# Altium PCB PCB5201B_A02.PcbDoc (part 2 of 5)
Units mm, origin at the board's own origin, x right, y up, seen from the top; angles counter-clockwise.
Board outline 115 x 60 mm, 6 copper layers (Top Layer, GND Layer 2, Signal Layer 3, Signal Layer 4, VCC Layer 5, Bottom Layer), stack 1.555 mm thick; 355 components, 250 nets, 1223 pads, 1070 vias.
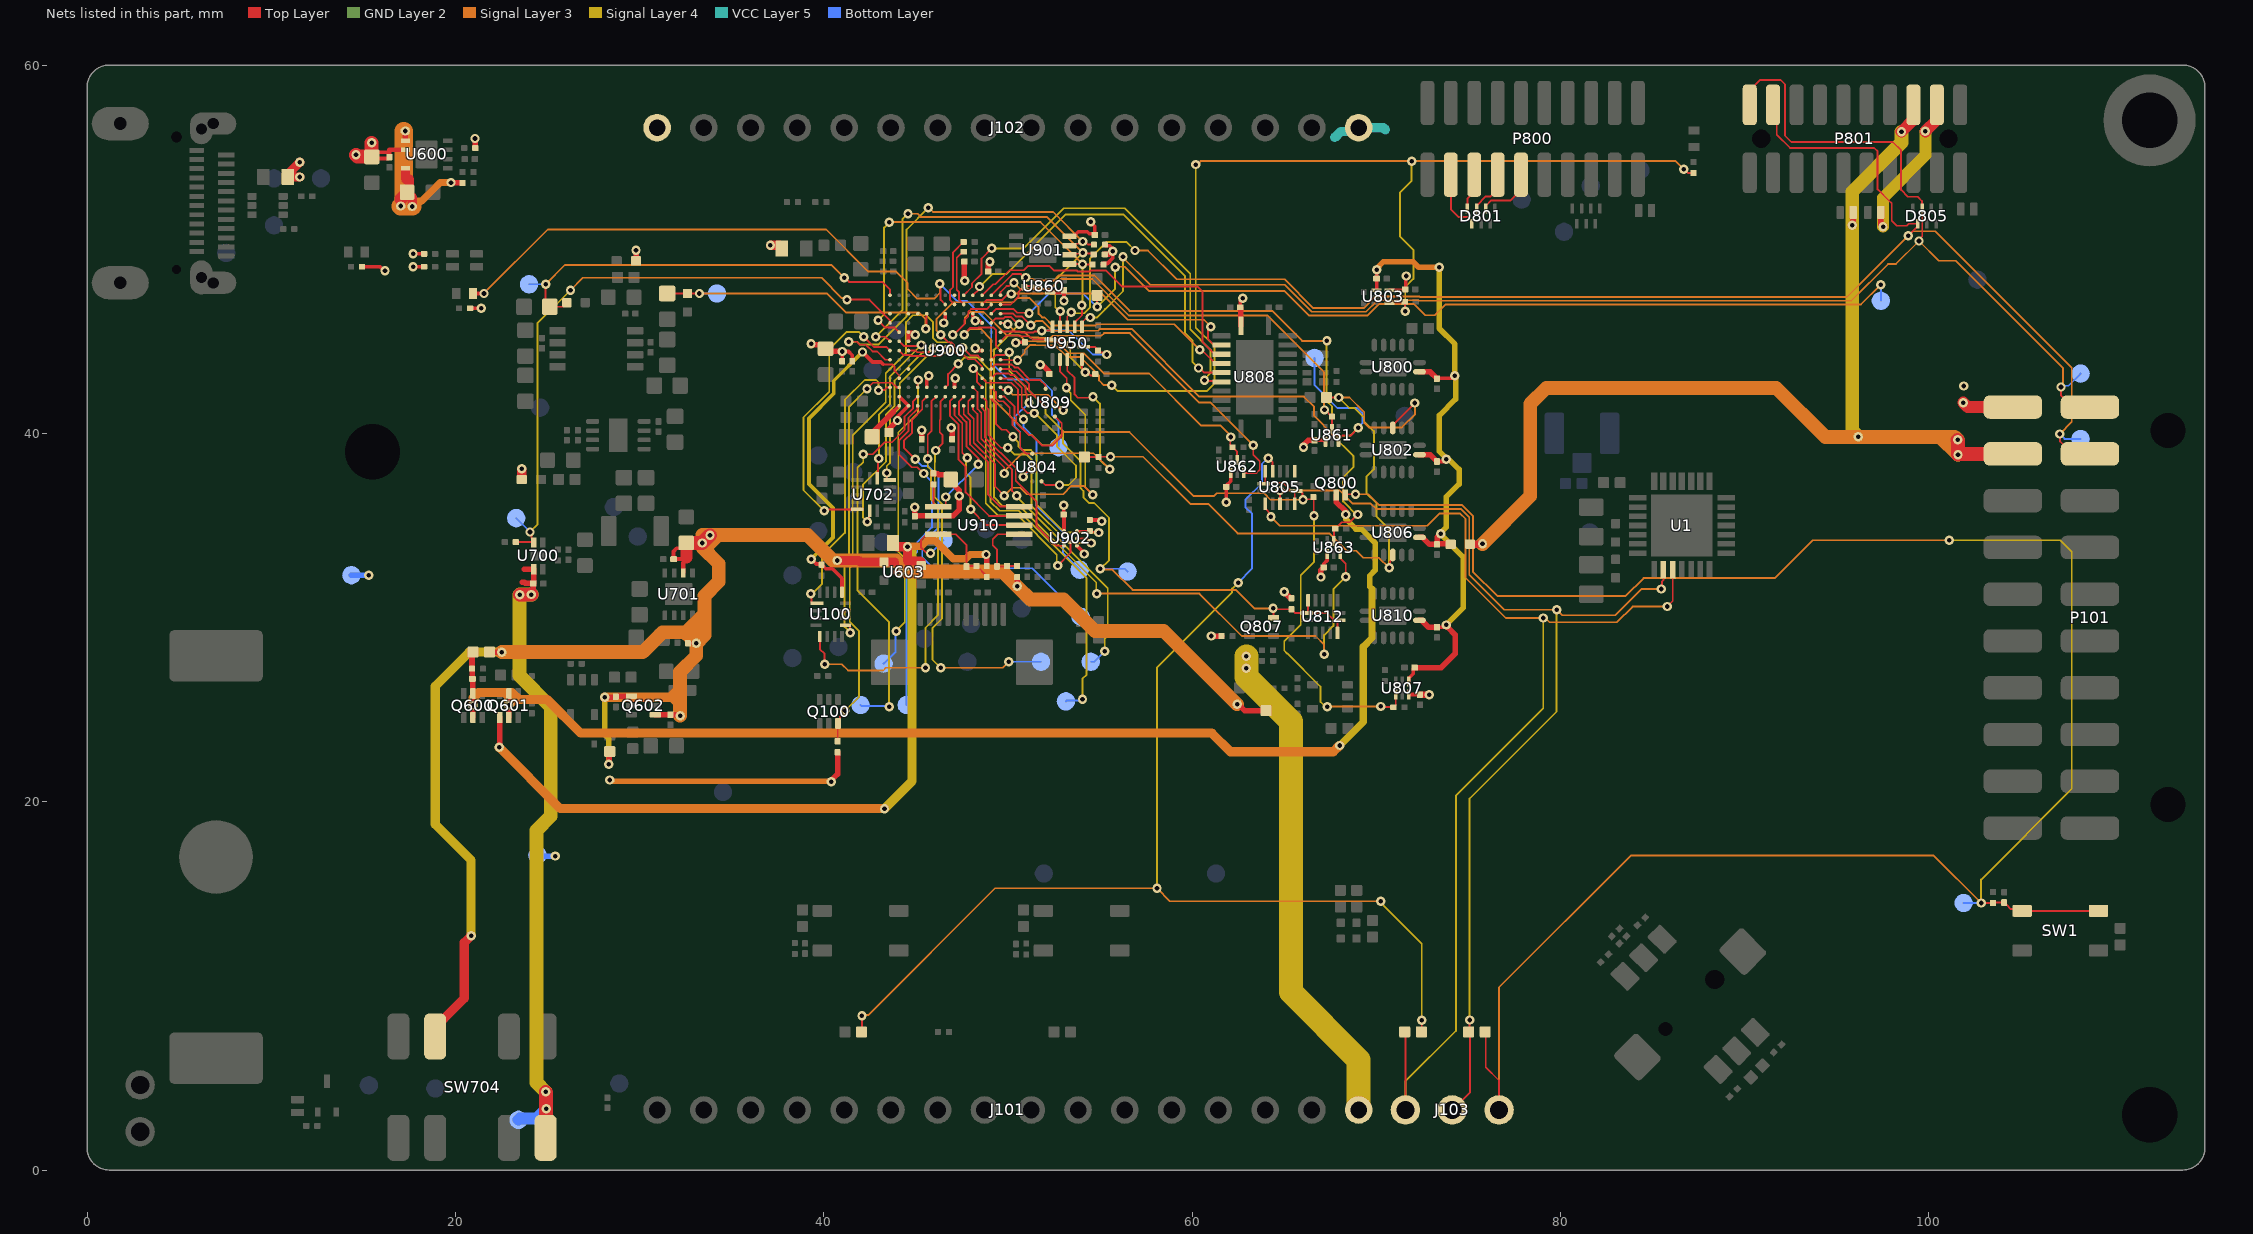
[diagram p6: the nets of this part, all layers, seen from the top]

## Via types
v1: diameter 0.508, hole 0.25, Top Layer to Bottom Layer, tented both sides, 1070 vias

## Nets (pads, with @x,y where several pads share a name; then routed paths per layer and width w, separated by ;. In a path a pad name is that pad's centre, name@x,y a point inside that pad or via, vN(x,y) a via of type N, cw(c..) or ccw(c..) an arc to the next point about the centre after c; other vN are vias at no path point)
3V3: C607.1 C807.1 C808.1 C860.1 C862.1 C864.1 C866.1 C868.1 C907.1 C908.1 C909.1 C910.1 C911.1 C914.1 C921.1 C922.1 C924.1 C925.1 C926.1 C927.1 C951.1 D807.1 J101.16 J102.16 L704.1 L900.1 P101.20 P801.3 R142.2 R601.2 R838.2 R840.2 R903.1 R906.2 R907.1 R908.1 R909.1 R912.1 R919.1 R920.1 R982.1 TPJ600.1 TPJ950.1 U600.1 U600.4 U803.6 U807.6 U808.1 U860.1 U861.1 U862.1 U863.1 U900.C6 U900.C9 U900.G3 U900.H11 U900.J11 U900.K3 U900.L4 U900.L7 U901.8 U902.A1 U902.E3 U910.2 | length 110.9
  Top Layer w0.2: R903.1@14.925,49.05 15.904,49.05 16.129,48.825 v1(16.175,48.825) ; U600.1@17.282,55.897 17.282,56.047 ; v1(17.7,49.05) R919.1@18.3,49.05 ; v1(17.7,49.75) R920.1@18.3,49.75 ; R912.1@20.8,46.8 v1(21.4,46.8) ; C924.1@41,43.925 41,44.325 41.125,44.45 41.35,44.45 41.55,44.25 C925.1@41.55,43.925 ; U900.H11@44.6,45 U900.J11@44.6,45.5 44.8,45.5 44.942,45.358 v1(44.974,45.358) ; U900.C9@45.6,42.5 45.6,43.025 v1(45.7,43.125) ; v1(46.525,46) 46.55,46 46.6,46.05 U900.L7@46.6,46.5 ; U900.C6@47.1,42.5 47.1,42.925 v1@47.175,43 ; U900.L4@48.1,46.5 48.1,46.35 48.25,46.2 48.25,46.15 v1(48.225,46.125) 48.475,46.125 U900.K3@48.6,46 ; v1(48.225,44.625) 48.35,44.5 U900.G3@48.6,44.5 ; v1(50.425,44.925) 50.45,44.95 C911.1@50.925,44.95 ; U860.1@52.3,47.65 52.925,47.65 C862.1@53.05,47.775 53.05,47.204 v1(53.047,47.201) ; v1@52.9,36.1 53.025,35.975 C914.1@53.025,35.6 53.05,35.575 U902.A1@53.05,34.7 ; U901.8@53.475,50.7 53.57,50.7 53.82,50.95 54.3,50.95 54.412,50.838 54.662,50.838 C951.1@54.722,50.778 54.722,51.238 54.55,51.411 v1@54.55,51.435 ; U902.E3@53.75,33.9 53.75,33.897 54.145,33.502 v1(54.145,33.455) ; R906.2@54.45,35.3 55.025,35.3 v1(55.1,35.225) ; v1(54.498,51.502) 54.498,51.487 v1@54.55,51.435 ; v1@54.55,51.475 v1@54.55,51.435 ; v1@54.625,51.36 v1@54.55,51.435 ; R908.1@55.139,49.175 55.192,49.228 55.403,49.228 55.696,49.521 55.696,49.896 v1(55.7,49.9) ; R909.1@55.25,50.225 55.284,50.191 55.53,50.191 55.725,49.996 v1@55.725,49.9 ; v1(61.866,36.253) 61.858,36.261 61.858,37.092 C860.1@61.85,37.1 61.85,37.15 62.1,37.4 U862.1@62.1,37.85 ; C808.1@62.625,46.85 62.625,47.225 v1(62.75,47.35) ; C864.1@66.65,39.625 67.175,39.625 U861.1@67.25,39.55 ; C866.1@67.15,32.725 67.15,32.925 67.35,33.125 U863.1@67.35,33.45 ; U803.6@70.725,47.775 71.495,47.775 71.5,47.78 C807.1@71.5,47.825 ; C807.1@71.575,47.825 71.6,47.85 71.6,48.525 v1(71.625,48.55) ; U807.6@71.763,25.825 71.763,25.82 72.319,25.82 C868.1@72.325,25.825
  Top Layer w0.25: 17.282,54.247 U600.4@17.282,54.397
  Top Layer w0.3: 17.282,56.047 v1(17.282,56.422) ; v1(19.757,53.622) 19.77,53.61 20.372,53.61 R601.2@20.382,53.597 R601.2@20.382,53.597 ; v1(39.312,44.865) 39.352,44.825 39.875,44.825 40.25,44.45 v1(41,44.45) v1@41.125,44.45 ; v1(40.4,21.085) 40.4,21.141 40.756,21.497 R142.2@40.756,22.683 ; v1(44.95,36) C922.1@44.95,35.5 44.975,35.525 U910.2@46.225,35.525 47.025,35.525 47.35,35.85 47.35,36.925 C921.1@46.825,37.45 ; C927.1@45.325,39.675 v1(45.325,40.175) ; R982.1@45.954,37.831 45.954,37.821 45.964,37.811 46.189,37.811 46.25,37.75 46.65,37.75 C921.1@46.9,37.5 ; v1(46.925,40.3) 46.975,40.25 C926.1@46.975,39.675 ; v1@47.634,48.316 C910.1@47.634,49.333 ; C908.1@48.925,48.8 48.925,49.225 v1(49.025,49.325) ; v1(51.748,43.738) 51.788,43.699 51.9,43.699 52.225,43.374 52.225,43.234 52.235,43.224 C909.1@52.255,43.224 ; R907.1@55.265,49.726 55.275,49.736 55.479,49.736 55.604,49.86 v1@55.665,49.86 ; v1(61.05,29) 61.052,28.998 61.599,28.998 R838.2@61.601,28.996 ; C808.1@62.625,46.85 62.65,46.825 U808.1@62.65,45.845 ; v1(65,31.4) 65.35,31.05 R840.2@65.4,31.05 ; v1(66.05,39.25) 66.05,39.375 66.3,39.625 C864.1@66.65,39.625 ; v1(67,32.2) 67,32.575 C866.1@67.15,32.725 ; D807.1@97.4,52 97.4,51.35 v1(97.525,51.225) ; L704.1@29.807,49.375 v1(29.807,49.95) L704.1@29.807,49.375
  Top Layer w0.35: C868.1@72.376,25.814 72.381,25.809 72.866,25.809 v1(72.875,25.8)
  Top Layer w0.5: v1(17.032,52.347) 17.034,52.349 C607.1@17.034,52.724 ; 17.282,53.8 17.282,54.247 ; C607.1@17.382,53.072 C607.1@17.382,53.097 ; 17.5,53.8 17.5,53.215 C607.1@17.382,53.097 ; v1(17.657,52.322) 17.657,52.822 C607.1@17.382,53.097 ; v1(37.106,50.217) 37.107,50.215 37.615,50.215 L900.1@37.814,50.016
  Top Layer w0.635: v1(99.825,56.4) 100.445,57.02 P801.3@100.445,57.841 ; v1(101.875,41.675) 102.12,41.43 P101.20@104.57,41.43
  Top Layer w0.7: C607.1@17.034,52.724 C607.1@17.382,53.072
  Signal Layer 3 w0.3: 17.25,53.225 17.85,52.625 ; v1(17.657,52.322) 17.697,52.362 17.912,52.362 18.175,52.625 ; v1(28.372,21.181) 28.411,21.142 28.558,21.142 28.576,21.124 v1@40.349,21.124
  Signal Layer 3 w0.4: 17.85,52.625 18.175,52.625 19.172,53.622 v1(19.757,53.622)
  Signal Layer 3 w1: v1@17.03,52.345 17.053,52.322 v1(17.657,52.322) ; 17.191,52.788 v1@17.191,56.422
  Signal Layer 4 w0.635: v1(97.525,51.225) 97.525,52.8 99.825,55.1 v1(99.825,56.4)
  Signal Layer 4 w1.3: v1(62.95,27.9) v1(62.95,27.25) 62.95,26.775 65.375,24.35 65.375,9.658 69.05,5.983 J101.16@69.05,3.262
  VCC Layer 5 w0.508: 67.759,56.076 68.076,56.393 68.841,56.393 J102.16@69.05,56.602 ; J102.16@68.877,56.602 J102.16@69.05,56.602 ; 70.5,56.5 70.398,56.602 J102.16@69.05,56.602
  Bottom Layer w0.3: TPJ600.1@14.353,32.302 v1(15.3,32.3) ; TPJ950.1@24.452,17.1 24.502,17.05 v1(25.425,17.05)
  other v1: 53.025,36.1 47.35,36.6 101.9,42.575 47.15,43 47.65,48.3
3V6_SW: C608.1 L702.1 Q601.1 R639.2 U603.B1 | length 47.3
  Top Layer w0.2: U603.B1@44.55,32.65 44.55,33.075
  Top Layer w0.3: v1@22.4,22.95 Q601.1@22.4,24.575 ; v1(48.815,33.427) 48.84,33.402 48.84,32.81 R639.2@48.85,32.8
  Top Layer w0.5: L702.1@43.765,34.05 43.965,33.85 v1(44.55,33.85) 44.55,33.075 45.225,33.075 C608.1@45.3,33
  Signal Layer 3 w0.4: v1(44.55,33.85) 44.571,33.871 45.3,33.871 45.604,34.175 46.05,34.175 47.025,33.2 47.725,33.2 47.952,33.427 v1(48.815,33.427)
  Signal Layer 3 w0.5: v1(22.375,22.95) 25.7,19.625 v1(43.3,19.625)
  Signal Layer 4 w0.5: v1(43.3,19.625) 44.8,21.125 44.8,33.598 44.55,33.848 v1(44.55,33.85)
3V6_SW_SENSE: C641.1 R639.1 R640.2 TP923.1 U910.4 | length 7.4
  Top Layer w0.1: v1(45.8,33.5) 45.6,33.5 45.275,33.825 45.275,34.2 45.6,34.525 U910.4@46.225,34.525 47.175,34.525 47.75,33.95 C641.1@47.75,32.775 47.775,32.8 R640.2@48.3,32.8 48.85,32.25 R639.1@48.85,32.2
  Bottom Layer w0.1: v1(45.8,33.5) TP923.1@46.5,34.2
5V: C600.1 C609.1 C611.1 C673.1 C674.1 C702.1 C703.1 C901.1 D806.1 J102.1 L600.2 L700.1 L800.1 P101.18 P801.5 Q602.1 Q602.4 R600.2 R622.2 R633.2 R681.2 R690.2 R700.2 SW704.6 U600.2 U603.A2 U603.B2 U701.2 U900.A11 U900.B12 | length 180.2
  Top Layer w0.2: C611.1@15.453,55.025 cw(c15.546,54.848) C611.1@15.592,55.042 ; 16.417,55.397 16.417,55.275 ; C702.1@31.845,33.231 31.845,33.595 32.011,33.761 32.311,33.761 C703.1@32.4,33.85 ; C702.1@31.858,33.185 32.512,33.185 32.475,33.075 32.375,32.975 ; R700.2@32.627,28.611 32.632,28.606 33.069,28.606 v1(33.075,28.6) ; 43.85,33.025 44.15,32.725 U603.B2@44.15,32.65 44.025,32.65 43.9,32.525 43.9,32.375 44.025,32.25 U603.A2@44.15,32.25 ; v1(44.002,40.702) 44.002,40.902 U900.A11@44.6,41.5 U900.B12@44.1,42 ; 16.417,55.275 16.417,54.985 16.357,54.925 15.554,54.925 C611.1@15.465,55.014 15.725,55.275 16.417,55.275
  Top Layer w0.25: 16.417,55.397 U600.2@17.282,55.397 ; U701.2@32.375,32.425 32.375,32.975
  Top Layer w0.3: v1(20.85,12.725) v1@20.852,12.723 ; v1(21.061,56.017) 21.072,56.007 21.072,55.507 R600.2@21.082,55.497 ; R622.2@21.85,28.125 v1(22.525,28.125) ; v1(28.1,25.675) 28.111,25.686 28.703,25.686 C674.1@28.713,25.697 ; v1(28.335,22.042) 28.357,22.065 28.357,22.699 R681.2@28.38,22.722 ; C674.1@28.713,25.697 28.713,25.715 28.723,25.725 Q602.1@29.55,25.725 ; Q602.4@30.85,24.725 C673.1@31.675,24.725 ; C673.1@31.675,24.721 31.685,24.711 32.105,24.711 32.145,24.671 v1(32.201,24.671) ; C901.1@43.55,40.05 43.55,40.25 v1(44.002,40.702) ; v1(50.5,31.7) R633.2@50.5,32.2 ; v1(62.447,25.294) 62.503,25.294 62.853,24.944 R690.2@64.021,24.944 ; v1(95.85,51.3) 95.9,51.35 D806.1@95.9,52
  Top Layer w0.4: L800.1@75.099,33.978 75.753,33.978 v1(75.775,34)
  Top Layer w0.5: L600.2@10.9,53.926 v1@11.549,53.926 ; L600.2@10.9,53.926 10.985,54.011 10.985,54.156 v1(11.551,54.722) ; SW704.6@18.9,7.25 18.9,7.873 19.246,8.219 19.369,8.219 20.475,9.325 20.475,12.35 v1@20.825,12.7 ; L700.1@23.6,37.5 v1(23.6,38.075) ; v1(40.74,33.1) 41.919,33.1 41.994,33.025 C609.1@43.275,33.025 43.85,33.025
  Top Layer w0.635: v1(98.525,56.375) 99.175,57.025 P801.5@99.175,57.841
  Top Layer w0.65: 32.55,33.25 C703.1@32.55,34.047
  Top Layer w0.75: v1(14.6,55.125) 14.686,55.039 15.44,55.039 C611.1@15.45,55.029 ; v1(15.45,55.775) C611.1@15.45,55.029 ; C611.1@15.465,55.014 C611.1@15.45,55.029 ; C703.1@32.535,34.061 C703.1@32.547,34.05 ; C703.1@32.55,34.047 C703.1@32.547,34.05 ; v1(33.825,34.475) v1(33.4,34.05) C703.1@32.547,34.05 ; v1@101.55,39.65 101.595,39.605 v1(101.595,38.84) 101.644,38.89 P101.18@104.57,38.89
  Signal Layer 3 w0.5: v1(28.1,25.675) 31.65,25.675 ; 32.075,26.15 32.075,26.1 31.65,25.675 ; 32.175,25.25 31.75,25.675 ; 32.201,25.675 31.75,25.675 ; 31.65,25.675 31.75,25.675
  Signal Layer 3 w0.75: v1(22.525,28.125) 30.175,28.125 31.25,29.2 32.475,29.2 ; v1(32.201,24.671) 32.201,25.675 32.201,27.051 33.075,27.925 v1@33.075,28.525 ; 33.5,29.95 33.5,29.55 32.812,28.863 ; 33.5,30.175 32.525,29.2 32.475,29.2 ; v1(33.825,34.475) v1@33.833,34.483 ; 34.575,34.475 34.25,34.475 33.6,33.825 v1@33.4,33.825 ; v1(62.447,25.294) 61.66,26.081 58.466,29.275 54.725,29.275 53.018,30.982 51.218,30.982 v1(50.5,31.7) 49.7,32.5 44.525,32.5 43.925,33.1 v1(40.74,33.1) 40.5,33.1 39.117,34.483 v1@33.833,34.483 ; v1(75.775,34) 78.362,36.587 78.362,41.602 79.235,42.475 91.725,42.475 94.39,39.81 100.625,39.81 ; v1@101.45,39.775 101.415,39.81 100.625,39.81 ; v1@101.576,38.976 v1(101.576,39.665) ; v1(101.595,38.84) 100.625,39.81 ; 32.475,29.2 32.812,28.863 ; 32.812,28.863 v1(33.075,28.6) 33.086,28.6 33.525,29.039 33.525,31.175 34.3,31.95 34.3,32.925 v1@33.4,33.825 ; v1@33.4,33.825 v1(33.4,34.05) 33.4,34.483 v1@33.833,34.483
  Signal Layer 4 w0.3: v1(28.1,25.675) 28.1,23.65 28.335,23.415 v1(28.335,22.042)
  Signal Layer 4 w0.5: v1(20.85,12.725) 20.85,16.825 18.9,18.775 18.9,26.275 20.75,28.125 v1(22.525,28.125)
  Signal Layer 4 w0.75: v1(96.175,39.825) 95.85,40.15 v1(95.85,51.3) 95.85,53.125 98.525,55.8 v1(98.525,56.375)
  other v1: 11.55,53.925
5V_DH_SW: C803.1 C805.1 C809.1 C827.1 C869.1 C870.1 L800.2 U800.14 U802.14 U803.1 U806.14 U807.1 U810.14 | length 39.9
  Top Layer w0.2: C869.1@70.019,48.403 70.022,48.406 70.022,48.89 v1(70.025,48.893) ; U803.1@70.025,47.775 70.022,47.775 70.022,48.347 C869.1@70.025,48.35 ; U807.1@71.763,26.525 71.763,26.7 72.009,26.946 72.009,27.224 72.035,27.25 C870.1@72.075,27.25 ; C827.1@73.3,29.475 73.675,29.475 v1(73.8,29.6) ; C805.1@73.3,38.475 73.675,38.475 v1(73.8,38.6) ; C803.1@73.325,43 74.15,43 v1(74.275,43.125)
  Top Layer w0.3: C870.1@72.089,27.284 73.534,27.284 74.293,28.043 74.293,29.057 73.9,29.45 v1@73.9,29.625 ; U810.14@72.35,29.85 72.475,29.85 72.85,29.475 C827.1@73.3,29.475 ; U806.14@72.35,34.35 72.525,34.35 72.9,33.975 C809.1@73.3,33.975 73.31,33.985 73.31,34.371 73.49,34.551 v1(73.511,34.551) ; U802.14@72.35,38.85 72.925,38.85 C805.1@73.3,38.475 ; U800.14@72.35,43.35 72.925,43.35 C803.1@73.3,42.975 C803.1@73.325,43 ; C809.1@73.31,34 74.028,34 L800.2@74.049,33.978
  Signal Layer 3 w0.3: v1(70.025,48.893) 70.025,48.949 70.157,49.081 70.157,49.097 70.385,49.325 72,49.325 72.3,49.025 v1(73.425,49.025)
  Signal Layer 4 w0.3: v1(73.425,49.025) 73.425,45.7 74.275,44.85 v1(74.275,43.125) 74.315,43.085 74.315,42.938 74.318,42.935 74.318,41.868 73.432,40.982 73.432,39.024 73.8,38.656 v1(73.8,38.6) ; v1(73.8,29.6) 74.725,30.525 74.725,33.3 73.511,34.514 73.511,34.607 73.8,34.897 73.8,36.55 74.5,37.25 74.5,38.05 v1@73.875,38.675
5V_SENSE: C635.1 R633.1 R634.2 U910.7 | length 4.2
  Top Layer w0.1: R633.1@50.5,32.8 R634.2@49.95,32.8 49.925,32.775 C635.1@49.4,32.775 49.4,33.7 49.182,33.918 49.182,34.263 49.444,34.525 U910.7@50.625,34.525
5V_SW: C610.1 Q600.2 Q600.5 Q601.2 Q601.5 Q800.5 R622.1 R623.2 | length 70.9
  Top Layer w0.3: C610.1@20.925,26.675 20.925,27.2 R623.2@20.9,27.225 20.9,28.075 R622.1@20.95,28.125 ; Q600.2@20.95,24.575 v1(20.95,25.225) 20.95,25.25 Q600.5@20.95,25.875 C610.1@20.95,26.65 ; Q601.2@22.9,24.575 v1(22.9,25.25) Q601.5@22.9,25.875 ; Q800.5@67.825,36.65 67.825,36.275 68.35,35.75 v1(68.35,35.6)
  Signal Layer 3 w0.5: v1(20.95,25.225) 20.95,25.626 21.249,25.925 22.675,25.925 22.9,25.7 v1(22.9,25.25) 23.2,25.55 23.45,25.55 ; 22.725,25.925 22.9,25.925 23.075,25.925 23.325,25.675 23.45,25.55 ; v1(68.012,23.052) 67.669,22.709 62.091,22.709 61.075,23.725 26.8,23.725 24.975,25.55 23.45,25.55
  Signal Layer 4 w0.3: v1(68.35,35.6) 68.35,35.35 68.9,34.8 69.2,34.8 69.95,34.05 69.95,32.575 69.643,32.268 69.643,31.682 69.775,31.55
  Signal Layer 4 w0.4: v1(68.012,23.052) 69.307,24.347 69.307,28.425 69.775,28.893 69.775,31.55
#RESET: R805.2 R809.1 R810.2 U802.4 U806.11 | length 39.3
  Top Layer w0.1: R810.2@54.15,38.725 R809.1@54.925,38.725 54.938,38.737 v1(55.575,38.737) ; R805.2@67.3,41.95 v1(67.975,41.95) ; v1(70.7,32.7) 70.748,32.748 70.748,33.023 70.9,33.175 U806.11@70.9,33.4 ; U802.4@70.9,40.3 70.9,40.45 v1(72.1,41.65)
  Signal Layer 3 w0.1: v1(55.575,38.737) 57.338,38.737 59.9,36.175 60.875,36.175 62.475,34.575 67.45,34.575 68.393,33.632 68.918,33.632 69.3,33.25 70.15,33.25 v1(70.7,32.7) ; v1(67.975,41.95) 68.55,41.95 69.35,41.15 69.35,40.575 69.6,40.325 71.4,40.325 72.1,41.025 v1(72.1,41.65)
  Signal Layer 4 w0.1: v1(67.975,41.95) 68.55,41.375 68.825,41.375 69.325,40.875 69.325,40.675 69.875,40.125 69.875,38.05 69.468,37.643 69.468,36.757 70.025,36.2 70.025,35.475 70.7,34.8 v1(70.7,32.7)
AEM_5V_#ENABLE: U900.L10
AEM_CALIBRATE0: U702.13 U900.G11 | length 13.4
  Top Layer w0.1: v1(42.368,35.213) 42.368,35.323 42.45,35.406 42.45,35.74 U702.13@42.5,35.79 ; U900.G11@44.6,44.5 44.992,44.5 45.083,44.409 45.672,44.409 45.863,44.6 v1@45.95,44.6
  Signal Layer 4 w0.1: v1(42.368,35.213) 42.368,35.216 42.125,35.459 42.125,37.214 43.388,38.476 43.388,41.038 43.85,41.5 43.85,42.875 45.375,44.4 45.681,44.4 45.915,44.635 v1(45.935,44.635)
AEM_CALIBRATE1: U702.5 U900.G12 | length 11.9
  Top Layer w0.1: v1(43.425,37.85) 43.425,37.525 43.475,37.475 U702.5@43.585,37.475 ; U900.G12@44.1,44.5 44.35,44.25 44.704,44.25 44.752,44.202 46.327,44.202 v1(46.675,44.55)
  GND Layer 2 w0.1: v1(43.425,37.85) v1@43.483,37.908
  Signal Layer 4 w0.1: v1(43.425,37.85) 43.425,38.231 43.6,38.406 43.6,40.875 44.125,41.4 44.125,42.725 45.593,44.193 46.318,44.193 v1(46.675,44.55)
AEM_CALIBRATE2: U702.6 U900.H12 | length 9.6
  Top Layer w0.1: U702.6@42.9,37.56 42.947,37.607 42.947,38.592 v1(42.995,38.639) ; U900.H12@44.1,45 44.35,44.75 45.25,44.75 v1(45.302,44.802)
  Signal Layer 4 w0.1: v1(42.995,38.639) 42.995,41.003 43.6,41.608 43.6,43.1 v1(45.302,44.802)
AEM_CALIBRATE3: U702.12 U900.G13 | length 15.7
  Top Layer w0.1: v1(40.024,35.799) 40.1,35.875 U702.12@41.815,35.875 ; v1(42.175,45.25) 42.725,44.7 43.4,44.7 U900.G13@43.6,44.5
  Signal Layer 4 w0.1: v1(40.024,35.799) 40.024,35.801 38.9,36.925 38.9,40.867 40.3,42.267 40.3,44.575 41.225,45.5 41.925,45.5 v1(42.175,45.25)
AEM_CURRENT_HIGH_GAIN: C720.1 R764.2 TP706.1 U900.N13 | length 23.2
  Top Layer w0.1: v1(24.9,48.1) 24.9,47.1 R764.2@25.125,46.875 25.825,46.875 C720.1@26.05,47.1 ; v1(41.117,48.445) 41.159,48.445 41.38,48.225 43.175,48.225 43.6,47.8 U900.N13@43.6,47.5
  Signal Layer 3 w0.1: v1(24.9,48.1) 25.951,49.151 40.411,49.151 v1(41.117,48.445)
  Bottom Layer w0.1: TP706.1@24,48.1 v1(24.9,48.1)
AEM_CURRENT_LOW_GAIN: C724.1 R768.2 TP707.1 U900.L9 | length 16.9
  Top Layer w0.1: R768.2@31.5,47.6 C724.1@32.6,47.6 v1(33.25,47.6) ; v1(45.53,45.687) 45.581,45.738 45.581,46.481 U900.L9@45.6,46.5
  Signal Layer 3 w0.1: v1(33.25,47.6) 40.175,47.6 41.2,46.575 42.125,46.575 45.15,46.575 45.53,46.195 v1(45.53,45.687)
  Bottom Layer w0.1: v1(33.25,47.6) TP707.1@34.2,47.6
AEM_SENSE_SELECT: U900.L13
AEM_SWITCH_POS: U900.L11
AEM_VMCU: C708.1 SW704.4 TP709.1 U700.1 | length 38.2
  Top Layer w0.3: 23.625,31.925 23.75,31.925 23.8,31.875 23.851,31.875 23.866,31.86 24.215,31.86 C708.1@24.225,31.85 ; 23.725,32.625 U700.1@24.25,32.625 24.25,31.86 24.24,31.85 C708.1@24.225,31.85 ; v1(24.125,31.25) 24.125,31.306 24.225,31.406 C708.1@24.225,31.85
  Top Layer w0.75: v1(23.491,31.24) 24.115,31.24 v1(24.125,31.25) ; SW704.4@24.9,1.75 24.925,1.775 24.925,4.225 v1(24.9,4.25)
  Signal Layer 4 w0.75: v1(24.125,31.25) 24.075,31.25 23.501,31.25 v1(23.491,31.24) 23.475,31.224 23.475,30.35 23.475,26.85 25.175,25.15 25.175,19.216 24.4,18.441 24.4,4.75 v1(24.9,4.25) 24.9,3.35 v1(24.925,3.325)
  Bottom Layer w0.635: TP709.1@23.425,2.725 23.495,2.795 24.395,2.795 v1(24.925,3.325) 24.9,3.35 v1(24.9,4.25)
AEM_VMCU_ENABLE: R763.2 TP715.1 U700.4 U900.K13 | length 35.5
  Top Layer w0.1: R763.2@23.279,34.098 24.227,34.098 U700.4@24.25,34.075 24.25,34.2 24.128,34.322 24.128,34.572 v1(24.05,34.65) ; v1(41.265,47.267) 42.48,47.267 43.596,46.15 43.596,46.004 U900.K13@43.6,46
  Signal Layer 3 w0.1: v1(26.25,47.775) 26.925,48.45 39.884,48.45 40.989,47.345 41.187,47.345 v1(41.265,47.267)
  Signal Layer 4 w0.1: v1(24.05,34.65) 24.45,35.05 24.45,45.975 v1(26.25,47.775)
  Bottom Layer w0.1: TP715.1@23.3,35.4 v1(24.05,34.65)
BC_ADC_SPI_CIPO: U900.B6 U910.9 | length 9.1
  Top Layer w0.1: U900.B6@47.1,42 46.85,41.75 46.85,40.951 47.325,40.476 47.325,38.575 47.7,38.2 47.7,36.8 48.975,35.525 U910.9@50.625,35.525
BC_ADC_SPI_COPI: U900.A6 U910.8 | length 8.8
  Top Layer w0.1: U900.A6@47.1,41.5 47.1,40.984 47.525,40.559 47.525,38.95 v1(47.8,38.675) ; v1(47.975,35.875) 48.825,35.025 U910.8@50.625,35.025
  Signal Layer 4 w0.1: v1@47.725,38.5 47.725,37.85 47.975,37.6 v1(47.975,35.875)
BC_ADC_SPI_CS: R982.2 U900.B5 U910.1 | length 8.9
  Top Layer w0.1: R982.2@45.954,37.231 45.954,36.125 46.054,36.025 U910.1@46.225,36.025 46.525,36.025 46.625,36.125 v1(46.625,36.55) ; U900.B5@47.6,42 47.35,41.75 47.35,41.017 47.75,40.617 47.75,39.3 48.4,38.65 v1(48.4,38.325)
  Bottom Layer w0.1: v1(46.625,36.55) 48.3,38.225 v1@48.3,38.3
BC_ADC_SPI_SCLK: U900.A5 U910.10 | length 7.3
  Top Layer w0.1: U900.A5@47.6,41.5 47.6,41.05 47.95,40.7 47.95,39.4 48.925,38.425 48.925,36.675 49.575,36.025 U910.10@50.625,36.025
BC_BUTTON_ENABLE: R981.1 U900.H1 U950.6 U950.12 | length 7.3
  Top Layer w0.1: U900.H1@49.6,45 49.932,45.332 50.574,45.332 50.626,45.28 51.17,45.28 51.35,45.1 U950.6@52.34,45.1 53.024,45.1 53.304,44.82 v1(53.386,44.82) ; U950.12@54.025,44.015 54.025,43.545 54.2,43.37 v1(54.2,43.321) ; v1@54.224,43.346 54.225,43.346 54.28,43.346 54.488,43.138 R981.1@54.653,43.138
  Signal Layer 4 w0.1: v1(53.386,44.82) 53.386,44.136 v1(54.2,43.321)
BC_DAC_OUT: U900.N6
BC_DBG_#RESET: LED903.1 TPJ956.1 U900.M7 | length 43.3
  Top Layer w0.1: v1(46.3,48.125) 46.35,48.075 46.35,47.25 U900.M7@46.6,47
  Top Layer w0.2: LED903.1@20.95,47.6 v1(21.55,47.6)
  Signal Layer 3 w0.1: v1(21.55,47.6) 25.025,51.075 40.125,51.075 42.41,48.79 43.935,48.79 44.55,48.175 44.55,47.85 45.075,47.325 46,47.325 46.3,47.625 v1(46.3,48.125)
  Bottom Layer w0.1: v1(46.3,48.125) 47.225,47.2 47.775,47.2 49.1,45.875 49.1,43.85 50.025,42.925 51.778,42.925 52.4,42.303 52.4,41 52.753,40.647 TPJ956.1@52.753,39.251
BC_DBG_TCK_SWCLK: TPJ954.1 U900.C10 | length 17
  Top Layer w0.1: U900.C10@45.1,42.5 45.1,42.775 45.05,42.825 45.05,42.85 45.1,42.9 v1(45.125,42.9) ; v1@45.225,42.852 v1@45.225,42.9
  Signal Layer 4 w0.1: v1(43.943,29.25) 43.943,29.293 44.4,29.75 44.4,33.225 44.05,33.575 44.05,40.05 45.125,41.125 v1(45.125,42.9)
  Bottom Layer w0.1: TPJ954.1@43.253,27.501 43.9,28.148 43.9,29.207 v1(43.943,29.25)
BC_DBG_TDO_SWO: TPJ955.1 U900.A10 | length 18.1
  Top Layer w0.1: U900.A10@45.1,41.5 45.1,41.342 44.595,40.837 44.595,40.129 44.1,39.634 44.1,38.845 44.783,38.162 45.088,38.162 v1(45.425,37.825)
  Bottom Layer w0.1: TPJ955.1@44.503,25.251 44.503,33.003 45.075,33.575 45.075,34.1 45.875,34.9 45.875,37.375 v1(45.425,37.825)
BC_DBG_TMS_SWDIO: TPJ953.1 U900.B10 | length 21
  Top Layer w0.1: v1(42.143,38.872) 42.672,38.872 43.325,39.525 43.708,39.525 44.395,40.212 44.395,40.92 44.85,41.375 44.85,41.75 U900.B10@45.1,42
  Signal Layer 4 w0.1: v1(42.143,38.872) 42.143,38.443 41.825,38.125 41.825,31.475 43.55,29.75 v1(43.55,25.164)
  Bottom Layer w0.1: TPJ953.1@42.001,25.251 42.045,25.207 43.506,25.207 v1(43.55,25.164)
BC_DISP_AVAILABLE: Q100.6 R142.1 U900.F3 | length 30.5
  Top Layer w0.1: R142.1@40.756,23.283 40.765,23.292 40.765,24.23 Q100.6@40.775,24.24 40.775,24.39 40.89,24.505 40.89,24.628 41.156,24.894 v1(41.156,24.932) ; v1(47.55,44.65) 47.975,44.225 48.375,44.225 U900.F3@48.6,44
  Signal Layer 4 w0.1: v1(41.156,24.932) 41.924,25.7 41.924,29.257 41.412,29.768 41.412,32.717 41.575,32.88 41.575,39.9 43.368,41.693 43.368,43.268 44.475,44.375 44.475,46.05 44.843,46.418 45.564,46.418 45.925,46.057 45.925,45.2 46.173,44.952 46.829,44.952 47.131,44.65 v1(47.55,44.65)
BC_DISP_COM: U900.E11
BC_DISP_PWR_ENABLE: R140.2 U100.13 U900.D12 | length 19.2
  Top Layer w0.1: R140.2@39.888,32.865 R140.2@39.888,32.875 ; 43.185,43.75 43.225,43.75 43.714,43.75 43.85,43.614 43.85,43.604 43.85,43.396 44.1,43.146 U900.D12@44.1,43
  Top Layer w0.2: v1(39.325,33.175) 39.335,33.175 39.596,32.914 39.849,32.914 R140.2@39.888,32.875 ; R140.2@39.888,32.865 39.948,32.805 39.958,32.805 40.114,32.65 40.475,32.65 40.99,32.135 U100.13@40.99,31.375 ; v1(42.106,44.422) 42.652,43.875 43.1,43.875 43.225,43.75
  Signal Layer 4 w0.2: v1(39.325,33.175) 40.5,34.35 40.5,35.95 39.2,37.25 39.2,40.814 40.55,42.164 40.55,42.866 v1(42.106,44.422)
BC_DISP_SPI_COPI: U100.5 U900.B8 | length 22.7
  Top Layer w0.1: U100.5@39.79,28.975 39.79,28.285 40.05,28.025 40.05,27.475 v1(40.048,27.473) ; v1(45.65,38.625) 45.65,39.925 45.85,40.125 45.85,41.75 U900.B8@46.1,42
  Signal Layer 3 w0.1: v1(40.048,27.473) 40.052,27.469 40.981,27.469 41.325,27.125 43.225,27.125 43.375,27.275 v1@45.52,27.275
  Signal Layer 4 w0.1: v1(45.525,27.275) 45.525,29.45 46.2,30.125 46.2,36.025 45.825,36.4 45.825,38.025 45.65,38.2 v1(45.65,38.625)
BC_DISP_SPI_CS: U100.9 U900.C12 | length 16.5
  Top Layer w0.1: U100.9@41.19,29.575 41.382,29.575 41.432,29.525 41.432,29.193 v1(41.444,29.181) ; v1(42.35,42.425) 42.675,42.75 43.704,42.75 43.954,42.5 U900.C12@44.1,42.5
  Signal Layer 4 w0.1: v1(41.444,29.181) 41.132,29.492 41.132,32.857 41.375,33.1 41.375,41.45 v1(42.35,42.425)
BC_DISP_SPI_SCLK: U100.1 U900.C13 | length 15.6
  Top Layer w0.1: v1(39.304,31.286) 39.34,31.25 39.34,30.825 39.39,30.775 U100.1@39.64,30.775 ; v1(42.975,42.35) 43.275,42.35 43.425,42.5 U900.C13@43.6,42.5
  Signal Layer 4 w0.1: v1(39.304,31.286) 39.377,31.286 39.9,31.809 39.9,33.35 41.15,34.6 41.15,41.819 42.231,42.9 42.85,42.9 42.975,42.775 v1(42.975,42.35)
BC_I2C_EXP_ENABLE: R950.1 U900.J1 U950.5 U950.13 | length 8.6
  Top Layer w0.1: U900.J1@49.6,45.5 49.6,45.532 50.656,45.532 50.708,45.48 51.394,45.48 51.444,45.53 51.783,45.53 v1(51.835,45.582) ; v1@51.848,45.598 52.375,45.598 52.425,45.648 U950.5@52.425,45.785 ; U950.13@54.11,44.7 54.71,44.7 54.9,44.51 54.9,44.497 55.01,44.387 55.158,44.387 55.258,44.287 v1(55.368,44.287)
  Bottom Layer w0.1: v1(51.835,45.582) 53.318,45.582 54.613,44.287 v1(55.368,44.287)
BC_I2C_EXP_SCL: D805.5 P101.17 P801.17 TPJ651.1 U950.3 | length 86.2
  Top Layer w0.1: U950.3@53.225,45.785 53.225,46.35 v1(53.45,46.575) ; P801.17@91.555,57.841 91.75,57.647 91.75,56.225 92.475,55.5 97.05,55.5 97.225,55.325 97.225,53.252 97.927,52.55 97.941,52.55 98,52.491 98,51.55 98.275,51.275 98.8,51.275 98.91,51.385 D805.5@99.4,51.385 99.4,51.25 v1(98.892,50.742) ; v1(107.114,39.967) 107.134,39.947 107.134,39.563 107.808,38.89 P101.17@108.76,38.89
  Signal Layer 3 w0.1: v1(56.902,49.932) 57.603,49.932 59.16,48.375 65.025,48.375 66.593,46.807 69.332,46.807 69.961,47.436 72.364,47.436 72.397,47.403 95.553,47.403 v1(98.892,50.742) 98.915,50.742 99.148,50.975 100.365,50.975 107.775,43.565 107.775,40.629 v1(107.114,39.967)
  Signal Layer 4 w0.1: v1(53.45,46.575) 53.5,46.525 54.145,46.525 54.45,46.83 54.45,49.475 55.375,50.4 56.435,50.4 v1@56.902,49.933
  Bottom Layer w0.1: v1(107.114,39.967) 107.381,39.7 TPJ651.1@108.25,39.7
BC_I2C_EXP_SDA: D805.3 P101.19 P801.19 TPJ650.1 U950.1 | length 84.7
  Top Layer w0.1: U950.1@54.025,45.785 54.025,46.025 54.214,46.214 54.39,46.214 v1(54.468,46.293) ; P801.19@90.285,57.841 90.285,58.635 90.85,59.2 91.955,59.2 92.2,58.955 92.2,56.175 92.55,55.825 98.05,55.825 98.5,55.375 98.5,53.225 98.875,52.85 99.4,52.85 99.63,52.62 D805.3@99.63,52.355 ; v1(99.475,50.45) 99.475,50.538 99.65,50.713 D805.3@99.65,52.215 ; v1(107.189,42.523) 107.189,42.048 107.808,41.43 P101.19@108.76,41.43
  Signal Layer 3 w0.1: v1(56.25,49.6) 56.25,49.55 57.725,48.075 65.034,48.075 66.502,46.607 69.447,46.607 70.076,47.236 72.281,47.236 72.314,47.203 95.803,47.203 97.8,49.2 98.225,49.2 v1(99.475,50.45) 100.55,49.375 101.475,49.375 107.3,43.55 107.3,42.744 107.189,42.633 v1(107.189,42.523)
  Signal Layer 4 w0.1: v1(54.468,46.293) 54.818,46.293 55.275,46.75 56.25,47.725 v1(56.25,49.6)
  Bottom Layer w0.1: v1(107.189,42.523) 107.258,42.591 107.593,42.591 TPJ650.1@108.25,43.248
BC_SPI_CIPO: U900.B3 U902.C3 | length 12.6
  Top Layer w0.1: U900.B3@48.6,42 48.85,41.75 48.85,41.396 48.95,41.296 48.95,39.9 49.625,39.225 v1(50,39.225) ; U902.C3@53.75,34.3 54.275,34.3 v1(54.525,34.05)
  Signal Layer 4 w0.1: v1(50,39.225) 50.375,38.85 51.025,38.85 51.275,38.6 51.275,36.075 53.3,34.05 v1(54.525,34.05)
BC_SPI_COPI: U900.C3 U902.D2 | length 16
  Top Layer w0.1: v1(48.125,43.525) 48.325,43.325 48.325,42.775 U900.C3@48.6,42.5 ; v1(52.7,32.825) 53.4,33.525 U902.D2@53.4,34.1
  Signal Layer 4 w0.1: v1(48.125,43.525) 48.8,42.85 48.8,36.2 49.45,35.55 50.525,35.55 52.652,33.423 52.652,32.873 v1(52.7,32.825)
BC_SPI_CS: R906.1 U900.B2 U902.A3 | length 12.5
  Top Layer w0.1: U900.B2@49.1,42 49.1,41.854 49.35,41.604 49.35,40.525 49.675,40.2 49.9,40.2 v1(50.275,39.825) ; U902.A3@53.75,34.7 R906.1@54.45,34.7 54.492,34.658 54.895,34.658 v1(54.937,34.617)
  Signal Layer 4 w0.1: v1(50.275,39.825) 50.575,39.525 50.575,39.3 50.775,39.1 51.25,39.1 51.55,38.8 51.55,36.15 53.083,34.617 v1(54.937,34.617)
BC_SPI_SCLK: U900.A3 U902.E1 | length 9.7
  Top Layer w0.1: U900.A3@48.6,41.5 48.6,41.364 48.75,41.214 48.75,39.8 50.425,38.125 50.425,37.431 51.55,36.306 51.55,34.975 52.625,33.9 U902.E1@53.05,33.9
BC_TRACECLK: TPJ957.1 U900.B7 | length 21.2
  Top Layer w0.1: v1(46.075,39.075) 46.443,39.443 46.443,39.924 46.3,40.067 46.3,40.725 46.35,40.775 46.35,41.75 U900.B7@46.6,42
  Signal Layer 3 w0.1: v1(46.35,27.275) 49.731,27.275 v1(50.053,27.597)
  Signal Layer 4 w0.1: v1(46.075,39.075) 46.05,39.05 46.05,38.456 46.032,38.438 46.032,36.543 46.425,36.15 46.425,29.95 45.9,29.425 45.9,27.725 v1(46.35,27.275)
  Bottom Layer w0.1: v1(50.053,27.597) 50.051,27.599 TPJ957.1@51.799,27.599
BC_TRACED0: TPJ958.1 U900.C7 | length 25.4
  Top Layer w0.1: U900.C7@46.6,42.5 46.75,42.65 46.75,43.225 v1(47.3,43.775)
  Signal Layer 4 w0.1: v1(47.3,43.775) 47.65,44.125 48.325,44.125 49.05,43.4 49.05,36.3 49.55,35.8 50.6,35.8 54.275,32.125 54.275,26.9 54.05,26.675 v1(54.05,25.556)
  Bottom Layer w0.1: TPJ958.1@53.15,25.45 53.203,25.503 53.997,25.503 v1(54.05,25.556)
BC_TRACED1: TPJ959.1 U900.C4 | length 18.4
  Top Layer w0.1: U900.C4@48.1,42.5 48.35,42.25 48.35,41.331 48.55,41.131 48.55,39.7 50.225,38.025 50.225,36.875 v1(50.475,36.625)
  Signal Layer 4 w0.1: v1(50.475,36.625) 50.475,36.55 55.425,31.6 55.425,29.025 55.262,28.862 v1(55.262,28.176)
  Bottom Layer w0.1: TPJ959.1@54.499,27.599 54.685,27.599 v1(55.262,28.176)
BC_TRACED2: TPJ960.1 U900.D3 | length 13.5
  Top Layer w0.1: U900.D3@48.6,43 48.85,42.75 50.192,42.75 50.55,42.392 50.55,41.075 v1@50.923,40.702
  Bottom Layer w0.1: v1(50.85,40.775) 50.85,40.35 51.55,39.65 51.55,36.075 53,34.625 53,33.497 TPJ960.1@53.899,32.598
BC_TRACED3: TPJ961.1 U900.B9 | length 20.5
  Top Layer w0.1: v1@45.003,38.578 44.35,39.231 44.35,39.601 44.795,40.047 44.795,40.754 45.35,41.309 45.35,41.75 U900.B9@45.6,42
  Bottom Layer w0.1: v1(44.978,38.603) 45.356,38.225 45.675,38.225 46.225,37.675 46.225,34.889 45.348,34.012 45.348,33.277 45.95,32.675 51.325,32.675 TPJ961.1@53.95,30.05
BC_UIF_BUTTON0: U900.B4 U950.9 | length 19.9
  Top Layer w0.1: U900.B4@48.1,42 47.85,41.75 47.85,41.1 48.15,40.8 48.15,39.5 49.3,38.35 49.3,37.125 v1(49.8,36.625) ; U950.9@52.825,44.015 52.825,43.375 53.197,43.003 53.197,42.499 v1(53.18,42.482)
  Signal Layer 3 w0.1: v1(49.8,36.625) 50.225,37.05 50.675,37.05 51.025,36.7 53,36.7 53.45,37.15 54.125,37.15 v1(54.6,36.675)
  Signal Layer 4 w0.1: v1(53.18,42.482) 53.18,42.411 53.416,42.174 53.416,41.809 54.2,41.025 54.2,37.075 v1(54.6,36.675)
BC_UIF_BUTTON1: U900.A4 U950.10 | length 18.6
  Top Layer w0.1: U900.A4@48.1,41.5 48.1,41.298 48.35,41.048 48.35,39.6 49.8,38.15 v1(49.8,37.825) ; U950.10@53.225,44.015 53.225,43.409 53.619,43.015 53.619,42.121 53.804,41.936 54.561,41.936 v1(54.621,41.996)
  Signal Layer 3 w0.1: v1@49.85,37.725 49.85,38 50.775,38.925 54.65,38.925 v1(55.525,38.05)
  Signal Layer 4 w0.1: v1(54.621,41.996) 55,41.617 55,38.575 v1(55.525,38.05)
BC_VCOM_CTS: U863.3 U900.K2 | length 40.1
  Top Layer w0.1: U900.K2@49.1,46 49.35,46.25 49.769,46.25 49.837,46.318 50.186,46.318 50.625,45.879 v1(50.625,45.925) ; v1@50.6,45.825 50.65,45.775 v1@50.675,45.8 ; U863.3@68.05,33.45 68.05,33.225 68.35,32.925 v1(68.35,32.225)
  Signal Layer 3 w0.1: v1(54.825,31.3) 60.4,31.3 62.7,29 66.706,29 67.175,28.531 v1(67.175,28)
  Signal Layer 4 w0.1: v1(50.625,45.925) 49.25,44.55 49.25,36.525 49.7,36.075 50.625,36.075 54.796,31.904 54.796,31.329 v1(54.825,31.3) ; v1(67.175,28) 67.175,29.05 67.675,29.55 67.675,31.55 v1(68.35,32.225)
BC_VCOM_CTS_DIR: R853.2 U863.5 U900.N2 | length 33.5
  Top Layer w0.1: U900.N2@49.1,47.5 50.25,48.65 50.71,48.65 50.89,48.47 v1(50.973,48.47) ; U863.5@67.7,34.15 67.7,34.75 R853.2@67.775,34.825 68.125,35.175 68.575,35.175 v1(69,35.6)
  Signal Layer 3 w0.1: v1(50.973,48.47) 51.051,48.392 51.361,48.392 51.45,48.303 52.478,48.303 52.757,48.582 54.678,48.582 56.61,46.65 64.35,46.65 65.975,45.025 v1(67.325,45.025)
  Signal Layer 4 w0.1: v1(67.325,45.025) 67.3,45 67.3,41.767 67.6,41.467 67.6,39.925 68.743,38.782 68.775,38.75 68.775,38.2 68.2,37.625 68.2,36.306 69,35.506 v1(69,35.6)
BC_VCOM_ENABLE: Q807.3 R840.1 TP930.1 U812.5 U812.6 U812.12 U812.13 U900.F2 | length 33.2
  Top Layer w0.1: U900.F2@49.1,44 49.35,44.25 49.8,44.25 49.95,44.4 v1(50.075,44.4) ; v1(64.4,30.5) v1@64.425,30.475 ; Q807.3@64.55,30 Q807.3@64.425,30 v1@64.425,30.475 ; U812.12@66.3,30.935 66.3,30.335 U812.13@66.215,30.25 ; U812.5@67.9,29.165 U812.6@67.9,29.85 ; U812.6@67.985,29.85 U812.6@67.9,29.85 ; v1@64.425,30.475 64.45,30.45 R840.1@65.4,30.45 65.6,30.25 U812.13@66.215,30.25 ; U812.13@66.215,30.25 67.325,30.25 67.725,29.85 U812.6@67.9,29.85
  Signal Layer 3 w0.1: v1(55.018,32.65) 55.066,32.602 55.673,32.602 56.775,31.5 62.375,31.5 63.375,30.5 v1(64.4,30.5)
  Signal Layer 4 w0.1: v1(50.075,44.4) 50.075,43.4 52.05,41.425 52.05,41.075 53,40.125 53,39.45 53.95,38.5 53.95,37.025 54.1,36.875 54.1,36.525 54.4,36.225 54.675,36.225 55.493,35.407 55.493,33.125 v1(55.018,32.65)
  Bottom Layer w0.1: v1(55.018,32.65) 56.35,32.65 TP930.1@56.5,32.5
BC_VCOM_RTS: U862.3 U900.K1 | length 19.1
  Top Layer w0.1: U900.K1@49.6,46 49.925,46 v1(50,45.925) ; U862.3@62.8,37.85 63.499,37.85 63.676,38.027 63.676,38.494 63.324,38.847 v1(63.324,39.367)
  Signal Layer 3 w0.1: v1(50,45.925) 50.4,45.525 50.899,45.525 51.218,45.206 51.655,45.206 51.672,45.189 52.314,45.189 52.425,45.3 55.075,45.3 55.225,45.45 56.625,45.45 60.4,41.675 61.016,41.675 v1(63.324,39.367)
BC_VCOM_RTS_DIR: R852.2 U862.5 U900.M2 | length 23.1
  Top Layer w0.1: v1(47,45.35) 47.056,45.35 47.64,45.935 47.64,46.14 47.85,46.35 47.85,46.604 47.996,46.75 48.85,46.75 U900.M2@49.1,47 ; v1(62.105,39.808) 62.075,39.778 62.075,39.375 R852.2@62.2,39.25 62.45,39 U862.5@62.45,38.55
  Signal Layer 3 w0.1: v1(47,45.35) 47.056,45.35 47.675,45.969 47.675,46.3 47.975,46.6 48.675,46.6 49.95,45.325 50.65,45.325 50.969,45.006 51.572,45.006 51.589,44.989 52.661,44.989 53.3,44.35 54.124,44.35 55.066,43.408 55.211,43.263 57.662,43.263 60.5,40.425 61.556,40.425 62.105,39.876 v1(62.105,39.808)
BC_VCOM_RXD: R882.2 TPJ606.1 U900.L2 | length 54.6
  Top Layer w0.1: U900.L2@49.1,46.5 49.35,46.75 50.319,46.75 50.512,46.557 51.118,46.557 v1(51.15,46.525) ; v1(54.843,46.874) 54.843,47.493 R882.2@54.85,47.5
  Signal Layer 3 w0.1: v1(55.826,49.024) 55.851,49.05 56.35,49.05 57.657,47.743 65.013,47.743 66.349,46.407 69.53,46.407 70.159,47.036 72.043,47.036 72.662,46.417 73.192,46.417 73.778,47.003 96.328,47.003 v1(97.4,48.075)
  Signal Layer 4 w0.1: v1@54.85,46.88 55.826,47.856 v1(55.826,49.024)
  Bottom Layer w0.1: v1(51.15,46.525) 52.221,47.596 54.104,47.596 54.826,46.874 v1(54.843,46.874) ; TPJ606.1@97.404,47.202 v1@97.404,48.075
BC_VCOM_RXD_DIR: R850.2 U860.5 U900.M1 | length 2.6
  Top Layer w0.1: U900.M1@49.6,47 50.156,47 50.568,47.412 50.568,47.668 50.722,47.822 50.79,47.822 50.9,47.932 R850.2@50.9,47.942 50.957,48 U860.5@51.6,48
BC_VCOM_TXD: TPJ607.1 U861.3 U900.L1 | length 30
  Top Layer w0.1: U900.L1@49.6,46.5 49.618,46.518 50.269,46.518 50.429,46.357 50.762,46.357 51.244,45.875 v1(51.25,45.875) ; U861.3@67.95,39.55 67.95,39.675 68.158,39.882 68.607,39.882 v1(69.025,40.3)
  Signal Layer 3 w0.1: v1(51.25,45.875) 51.288,45.875 51.513,46.1 51.889,46.1 52.414,45.575 54.9,45.575 55,45.675 56.725,45.675 60.4,42 66.075,42 66.625,41.45 66.625,40.95 67.7,39.875 68.6,39.875 v1(69.025,40.3)
  Bottom Layer w0.1: TPJ607.1@66.653,44.101 66.653,42.622 67.9,41.375 68.975,41.375 69.25,41.1 69.25,40.563 69.025,40.338 v1(69.025,40.3)
BC_VCOM_TXD_DIR: R851.2 U861.5 U900.N1 | length 23.7
  Top Layer w0.1: U900.N1@49.6,47.5 49.6,47.675 49.93,48.005 50.054,48.005 50.223,48.173 v1(50.333,48.173) ; v1(67.193,41.275) 67.227,41.275 67.59,40.912 R851.2@67.6,40.912 U861.5@67.6,40.25
  Signal Layer 3 w0.1: v1(50.333,48.173) 50.657,47.85 52.308,47.85 52.84,48.382 54.595,48.382 56.577,46.4 64.1,46.4 67.175,43.325 67.175,41.293 v1(67.193,41.275)
BOARD_ID_SCL: R907.2 U900.H13 U901.6 U950.4 | length 24.8
  Top Layer w0.1: v1(42.825,45.25) 43.35,45.25 U900.H13@43.6,45 ; U950.4@52.825,45.785 52.83,45.79 52.83,46.622 v1(52.836,46.627) ; U901.6@53.345,49.7 53.401,49.756 54.019,49.756 v1(54.075,49.813) ; v1@54.1,49.775 54.106,49.769 54.621,49.769 R907.2@54.665,49.726
  Signal Layer 3 w0.1: v1(44.575,51.925) 45.094,51.925 45.269,51.75 52.138,51.75 v1(54.075,49.813)
  Signal Layer 4 w0.1: v1(42.825,45.25) 44.275,46.7 44.275,51.625 v1(44.575,51.925) ; v1(52.836,46.627) 52.806,46.627 52.575,46.858 52.575,48.312 v1(54.075,49.813)
BOARD_ID_SDA: R908.2 U900.J12 U901.5 U950.2 | length 23.3
  Top Layer w0.1: v1(42.95,46.15) 43.35,45.75 43.85,45.75 U900.J12@44.1,45.5 ; U901.5@53.345,49.2 53.349,49.196 54.049,49.196 54.065,49.18 54.587,49.18 R908.2@54.598,49.168 ; U950.2@53.625,45.785 53.625,46.025 54.025,46.425 54.025,46.95 v1(54.02,46.955)
  Signal Layer 3 w0.1: v1(43.55,51.475) 51.77,51.475 v1(54.054,49.191)
  Signal Layer 4 w0.1: v1(42.95,46.15) 43.276,46.476 43.276,51.177 43.55,51.451 v1(43.55,51.475) ; v1(54.02,46.955) 54.054,46.99 v1(54.054,49.191)
BOARD_ID_WP: R909.2 U900.F13 U901.7 | length 23.6
  Top Layer w0.1: v1(41.35,44.975) 41.8,44.975 41.948,44.827 42.283,44.817 42.65,44.45 42.9,44.45 43.35,44 U900.F13@43.6,44 ; U901.7@53.345,50.2 53.445,50.3 53.84,50.3 53.96,50.421 v1(54.071,50.421) ; v1@54.071,50.41 54.191,50.41 v1@54.259,50.342 ; v1@54.175,50.3 54.217,50.342 v1@54.259,50.342 ; R909.2@54.676,50.251 54.351,50.251 v1@54.259,50.342
  Signal Layer 3 w0.1: v1(45.675,52.25) 45.713,52.25 45.938,52.025 52.466,52.025 v1(54.071,50.421)
  Signal Layer 4 w0.1: v1(41.35,44.975) 41.825,44.975 41.975,44.825 42.956,44.825 44.5,46.369 44.5,51.075 v1(45.675,52.25)
BOARD_VER0: R930.1 U900.M5 | length 3.2
  Top Layer w0.1: U900.M5@47.6,47 47.35,47.25 47.35,47.675 47.225,47.8 47.225,49.529 47.45,49.753 47.492,49.753 R930.1@47.602,49.863
BOARD_VER1: R931.1 U900.M6 | length 3.8
  Top Layer w0.1: U900.M6@47.1,47 46.85,47.25 46.85,47.775 47.025,47.95 47.025,49.835 47.59,50.4 R931.1@47.6,50.4
DBG_VREGO: C902.1 U900.A12 | length 2.4
  Top Layer w0.1: C902.1@42.55,39.875 42.6,39.825 C902.1@42.625,39.825
  Top Layer w0.2: 43.778,41.178 U900.A12@44.1,41.5
  Top Layer w0.3: C902.1@42.625,39.825 42.625,40.025 43.778,41.178
DEBUG_#RESET_C2CKPS: C8.1 J103.3 Q800.6 R9.2 R307.1 SW1.1 SW1.2 TP154.1 | length 114.6
  Top Layer w0.1: Q800.6@68.325,36.65 68.375,36.7 v1(68.875,36.7) ; R307.1@75.95,7.425 75.95,5.581 76.67,4.861 76.67,3.53 J103.3@76.75,3.45 ; v1(102.85,14.5) R9.2@103.5,14.5 103.525,14.525 C8.1@104.1,14.525 104.1,14.505 104.21,14.395 104.23,14.395 104.459,14.166 104.984,14.166 SW1.1@105.075,14.075 SW1.2@109.225,14.075
  Signal Layer 3 w0.1: v1(68.875,36.7) 69.583,36.7 70.176,36.107 74.668,36.107 75.25,35.525 75.25,32.5 76.575,31.175 83.55,31.175 84.518,32.143 91.643,32.143 93.7,34.2 v1(101.125,34.2) ; J103.3@76.525,3.625 76.67,3.77 76.67,9.92 83.825,17.075 100.275,17.075 v1(102.85,14.5)
  Signal Layer 4 w0.1: v1(101.125,34.2) 101.128,34.203 107.147,34.203 107.775,33.575 107.775,20.694 102.85,15.769 v1(102.85,14.5)
  Bottom Layer w0.1: TP154.1@101.9,14.5 v1(102.85,14.5)
DEBUG_#RESET_IN: U808.7 U900.N5 | length 23.7
  Top Layer w0.1: U900.N5@47.6,47.5 48.05,47.95 48.05,48.15 48.575,48.675 48.575,49.5 v1(49.125,50.05) ; v1(60.676,42.885) 60.719,42.842 61.563,42.842 U808.7@61.605,42.8
  Signal Layer 4 w0.1: v1(49.125,50.05) 50.85,50.05 53.025,52.225 56.35,52.225 59.9,48.675 59.9,45.65 61,44.55 61,43.272 60.676,42.949 v1(60.676,42.885)
DEBUG_DH_SW_ENABLE: R817.2 R900.1 U803.4 U900.F1 | length 63.4
  Top Layer w0.1: U900.F1@49.6,44 50.05,44 50.075,43.975 50.522,43.975 v1(50.523,43.977) ; U803.4@70.725,47.075 70.762,47.112 71.512,47.112 R817.2@71.575,47.175 ; R817.2@71.55,47.15 71.565,47.135 71.565,46.657 v1(71.579,46.643) ; v1(86.7,54.35) 86.737,54.35 86.947,54.14 R900.1@87.235,54.14
  Signal Layer 3 w0.1: v1(50.523,43.977) 50.919,44.373 50.919,44.514 51.211,44.806 51.489,44.806 51.506,44.789 52.578,44.789 53.217,44.15 53.927,44.15 54.95,43.127 54.95,42.875 55.2,42.625 v1(55.646,42.625) ; v1(60.2,54.6) 60.276,54.6 60.463,54.786 v1(71.924,54.786) 86.264,54.786 v1(86.7,54.35)
  Signal Layer 4 w0.1: v1(55.646,42.625) 55.971,42.3 60.81,42.3 61.225,42.715 61.225,44.725 60.2,45.75 v1(60.2,54.6) ; v1@71.525,46.65 71.582,46.707 71.582,47.951 72.018,48.387 72.018,49.972 71.3,50.69 71.3,53.1 71.924,53.724 v1(71.924,54.786)
DEBUG_MCU_SW_ENABLE: R814.2 R815.2 U805.5 U805.6 U805.12 U805.13 U807.4 U900.G1 | length 50.2
  Top Layer w0.1: v1(47.625,45.35) 47.625,45.4 47.957,45.732 48.388,45.732 48.406,45.75 49.225,45.75 49.35,45.625 49.35,44.75 U900.G1@49.6,44.5 ; U805.13@63.89,37.27 63.975,37.355 U805.12@63.975,37.955 ; U805.13@63.945,37.325 64.95,37.325 65.405,36.87 U805.6@65.66,36.87 ; U805.5@65.575,36.185 65.575,36.785 U805.6@65.66,36.87 ; v1(66.625,35.525) 66.608,35.542 66.608,36.525 R815.2@66.59,36.542 66.59,36.532 66.48,36.422 66.047,36.422 v1(66.025,36.4) 66.005,36.42 66.005,36.745 65.95,36.8 65.95,36.82 65.9,36.87 U805.6@65.66,36.87 ; v1(70.25,25.175) 70.272,25.152 70.91,25.152 R814.2@70.932,25.13 ; R814.2@70.925,25.175 70.987,25.175 71.063,25.251 U807.4@71.063,25.825
  Signal Layer 3 w0.1: v1(47.625,45.35) 47.95,45.675 48.525,45.675 49.075,45.125 49.075,41.994 51.162,39.907 51.312,39.907 51.862,39.357 52.31,39.357 53.028,40.075 56.604,40.075 60.072,36.607 61.207,36.607 61.35,36.75 63.911,36.75 64.261,36.4 v1(66.025,36.4) ; v1@67.425,25.175 67.431,25.169 70.244,25.169 v1(70.25,25.175)
  Signal Layer 4 w0.1: v1(66.625,35.525) 66.625,33.025 65.907,32.307 65.907,29.607 65.007,28.707 65.007,28.212 65.176,28.043 65.188,28.043 66.975,26.256 66.975,25.425 67.238,25.162 v1(67.342,25.162)
DEBUG_RESET_#OE: U804.A1 U900.D1 | length 9.8
  Top Layer w0.1: U900.D1@49.6,43 49.625,42.975 50.25,42.975 50.75,42.475 50.75,41.425 51.075,41.1 v1(51.425,41.1) ; U804.A1@51.825,37.4 52.025,37.2 v1(52.8,37.2)
  Signal Layer 4 w0.1: v1(51.425,41.1) 51.475,41.1 52.675,39.9 52.675,39.281 53.7,38.256 53.7,37.6 53.3,37.2 v1(52.8,37.2)
DEBUG_TCK_SWCLK_#OE: U809.A1 U900.B1 | length 6.3
  Top Layer w0.1: U900.B1@49.6,42 49.817,42 50.35,41.467 50.35,40.975 50.457,40.868 50.457,40.612 50.463,40.607 50.463,40.587 51.15,39.9 51.3,39.9 51.85,39.35 52.425,39.35 52.925,39.85 52.925,40.55 U809.A1@52.55,40.925
DEBUG_TCK_SWCLK_C2CK: J103.2 R307.2 U1.9 U805.3 | length 57.2
  Top Layer w0.1: U805.3@64.775,36.185 v1@64.775,36.75 ; J103.2@74.13,3.262 75.1,4.232 75.1,7.5 75.075,7.525 v1(75.075,8.15) ; v1(85.475,31.55) 85.516,31.591 85.516,31.954 85.6,32.038 U1.9@85.6,32.725
  Signal Layer 3 w0.1: v1@64.825,36.9 68.025,36.9 68.732,36.193 69.707,36.193 70,35.9 74.592,35.9 75.05,35.442 75.05,32.325 76.95,30.425 v1(79.8,30.425) 80.1,30.125 82.975,30.125 84.4,31.55 v1(85.475,31.55)
  Signal Layer 4 w0.1: v1(75.075,8.15) 75.075,20.175 79.8,24.9 v1(79.8,30.425)
  other v1: 64.775,36.9
DEBUG_TCK_SWCLK_IN: U808.4 U900.N3 | length 17.3
  Top Layer w0.1: U900.N3@48.6,47.5 49.2,48.1 49.325,48.1 50.086,48.861 50.727,48.861 50.728,48.863 50.863,48.863 51.1,49.1 52.25,49.1 52.495,48.855 53.732,48.855 53.789,48.798 54.471,48.798 54.523,48.85 55.319,48.85 56.199,47.97 60.308,47.97 60.575,47.703 60.575,44.95 61.225,44.3 U808.4@61.605,44.3
DEBUG_TCK_SWCLK_OUT: U809.B1 U900.C1 | length 4.5
  Top Layer w0.1: U900.C1@49.6,42.5 49.75,42.35 v1(50.025,42.35) v1@50.05,42.325 ; U809.B1@52.55,41.425 52.737,41.425 52.9,41.263 v1(53,41.263)
  Signal Layer 3 w0.1: v1(50.025,42.35) 50.275,42.1 52.163,42.1 v1(53,41.263)
DEBUG_TDI_#OE: U809.B2 U900.E1 | length 3.5
  Top Layer w0.1: U900.E1@49.6,43.5 50.125,43.5 50.25,43.375 50.449,43.375 51.153,42.67 51.153,42.322 U809.B2@52.05,41.425
DEBUG_TDI_C2DPS: R305.1 R306.1 U805.11 | length 67.2
  Top Layer w0.1: R305.1@42.05,7.5 42.075,7.525 v1(42.075,8.375) ; v1(64.142,38.65) 64.162,38.65 64.375,38.436 U805.11@64.375,37.955 ; R306.1@72.425,7.5 72.475,7.55 v1(72.475,8.125)
  Signal Layer 3 w0.1: v1(42.075,8.375) 42.111,8.411 42.411,8.411 49.3,15.3 v1(58.1,15.3) 58.8,14.6 v1(70.25,14.6)
  Signal Layer 4 w0.1: v1(58.1,15.3) 58.1,27.3 62.175,31.375 62.175,31.575 v1(62.5,31.9) ; v1(70.25,14.6) 70.25,14.524 72.475,12.299 v1(72.475,8.125)
  Bottom Layer w0.1: v1(62.5,31.9) 63.25,32.65 63.25,35.625 ; 63.262,35.638 62.9,36 62.9,36.4 63.8,37.3 63.8,38.35 64.1,38.65 v1(64.142,38.65)
DEBUG_TDI_IN: U808.6 U900.N4 | length 21.4
  Top Layer w0.1: U900.N4@48.1,47.5 48.461,47.861 v1(48.461,47.975) ; v1(60.354,43.554) 60.416,43.554 60.67,43.3 U808.6@61.605,43.3
  Signal Layer 4 w0.1: v1(48.461,47.975) 49.139,48.653 49.903,48.653 53.145,51.895 56.255,51.895 59.625,48.525 59.625,45.45 60.031,45.044 60.031,43.877 v1(60.354,43.554)
DEBUG_TDI_OUT: U809.D2 U900.E2 | length 3.7
  Top Layer w0.1: U900.E2@49.1,43.5 49.35,43.75 50.194,43.75 50.362,43.582 50.524,43.582 51.209,42.898 51.762,42.898 52.05,42.61 U809.D2@52.05,42.425
DEBUG_TDO_SWO: U805.8
DEBUG_TDO_SWO_IN: U808.5 U900.E3 | length 21.9
  Top Layer w0.1: v1(46.35,45.35) 46.75,44.95 46.92,44.95 47.085,44.785 47.085,44.465 47.325,44.225 47.645,44.225 47.845,44.025 48.2,44.025 48.6,43.625 U900.E3@48.6,43.5 ; v1(60.424,44.537) 60.513,44.537 61.25,43.8 U808.5@61.605,43.8
  Signal Layer 3 w0.1: v1(46.35,45.35) 46.125,45.575 46.125,46.225 47.025,47.125 50.294,47.125 50.519,47.35 51.183,47.35 51.671,46.862 51.671,46.488 51.859,46.3 51.987,46.3 52.43,45.857 54.749,45.857 54.817,45.925 59.036,45.925 v1(60.424,44.537)
DEBUG_TMS_SWDIO_#OE: U804.B2 U900.D2 | length 8.8
  Top Layer w0.1: U900.D2@49.1,43 49.35,43.25 50.05,43.25 50.125,43.175 50.35,43.175 50.953,42.572 50.953,42.23 51.025,42.158 51.025,41.8 v1(51.15,41.675) ; v1@50.775,37.65 51.025,37.9 U804.B2@51.325,37.9
  Bottom Layer w0.1: v1(50.825,37.65) 51.275,38.1 51.275,38.625 50.675,39.225 50.675,40.075 50.35,40.4 50.35,40.875 v1(51.15,41.675)
DEBUG_TMS_SWDIO_C2D: J103.1 R306.2 U1.10 U805.1 | length 63.7
  Top Layer w0.1: U805.1@63.975,36.185 63.975,35.925 v1@64.285,35.615 ; R306.2@71.525,7.425 71.59,7.36 J103.1@71.59,3.262 71.59,3.215 J103.1@71.55,3.175 ; v1(85.8,30.6) 86.1,30.9 U1.10@86.1,32.725
  Signal Layer 3 w0.1: v1(64.285,35.479) 64.775,34.989 72.764,34.989 73.425,35.65 74.559,35.65 74.85,35.359 74.85,32.175 77.05,29.975 v1(79.075,29.975) 79.185,29.975 79.41,29.75 83.075,29.75 83.925,30.6 v1(85.8,30.6)
  Signal Layer 4 w0.1: J103.1@71.59,3.262 71.59,4.815 74.325,7.55 74.325,20.325 79.075,25.075 v1(79.075,29.975)
DEBUG_TMS_SWDIO_IN: U808.3 U900.M3 | length 15
  Top Layer w0.1: U900.M3@48.6,47 48.85,47.25 49.704,47.25 50.029,47.575 v1(50.175,47.575) ; v1(61.025,45.8) 60.875,45.65 60.875,45.125 61.2,44.8 U808.3@61.605,44.8
  Signal Layer 3 w0.1: v1(50.175,47.575) 50.196,47.596 55.098,47.596 56.519,46.175 60.65,46.175 v1(61.025,45.8)
DEBUG_TMS_SWDIO_OUT: U804.D2 U900.C2 | length 4.9
  Top Layer w0.1: U900.C2@49.1,42.5 49.35,42.25 49.35,41.9 49.35,41.896 49.496,41.75 49.748,41.75 50.1,41.398 50.1,40.925 50.25,40.775 50.25,40.45 50.675,40.025 50.675,39.225 51,38.9 U804.D2@51.325,38.9
DEBUG_TRACECLK: D801.2 P800.12 | length 3.2
  Top Layer w0.1: D801.2@75.95,52.215 75.95,52.35 76.25,52.65 77.3,52.65 77.865,53.215 P800.12@77.865,54.05
DEBUG_TRACED0: D801.3 P800.14 | length 2.5
  Top Layer w0.1: D801.3@75.45,52.215 75.45,52.375 75.95,52.875 76.225,52.875 76.595,53.245 P800.14@76.595,54.05
DEBUG_TRACED1: D801.4 P800.16 | length 2
  Top Layer w0.1: D801.4@74.95,52.215 74.95,52.75 75.325,53.125 P800.16@75.325,54.05
DEBUG_TRACED2: D801.5 P800.18 | length 3.4
  Top Layer w0.1: P800.18@74.055,54.05 74.055,52.17 74.475,51.75 75,51.75 75.2,51.55 D801.5@75.2,51.385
